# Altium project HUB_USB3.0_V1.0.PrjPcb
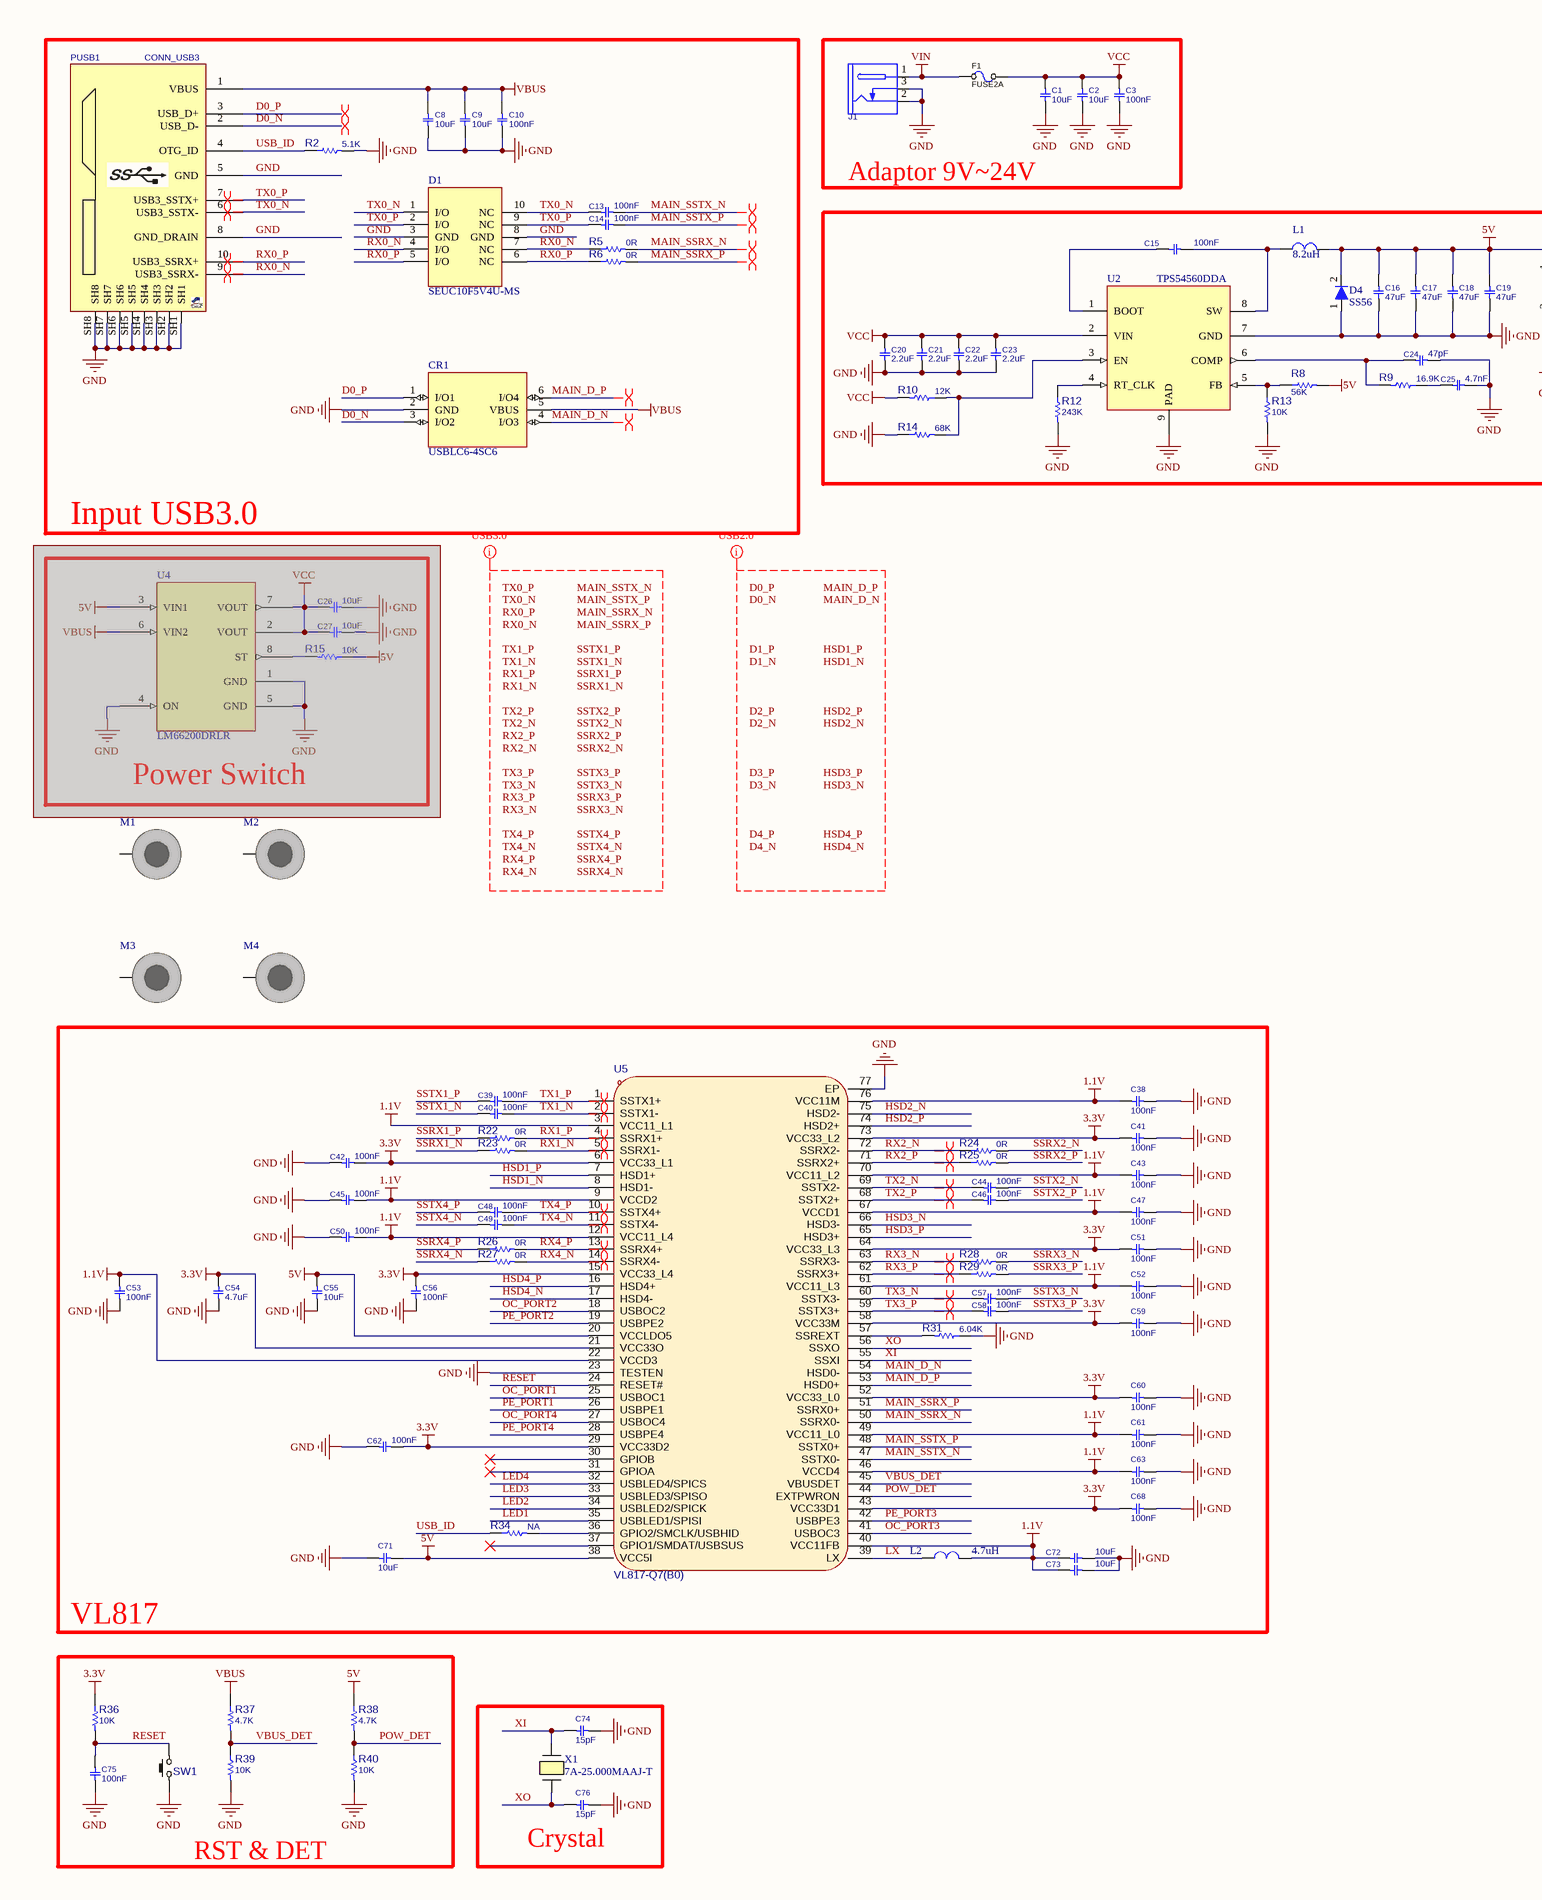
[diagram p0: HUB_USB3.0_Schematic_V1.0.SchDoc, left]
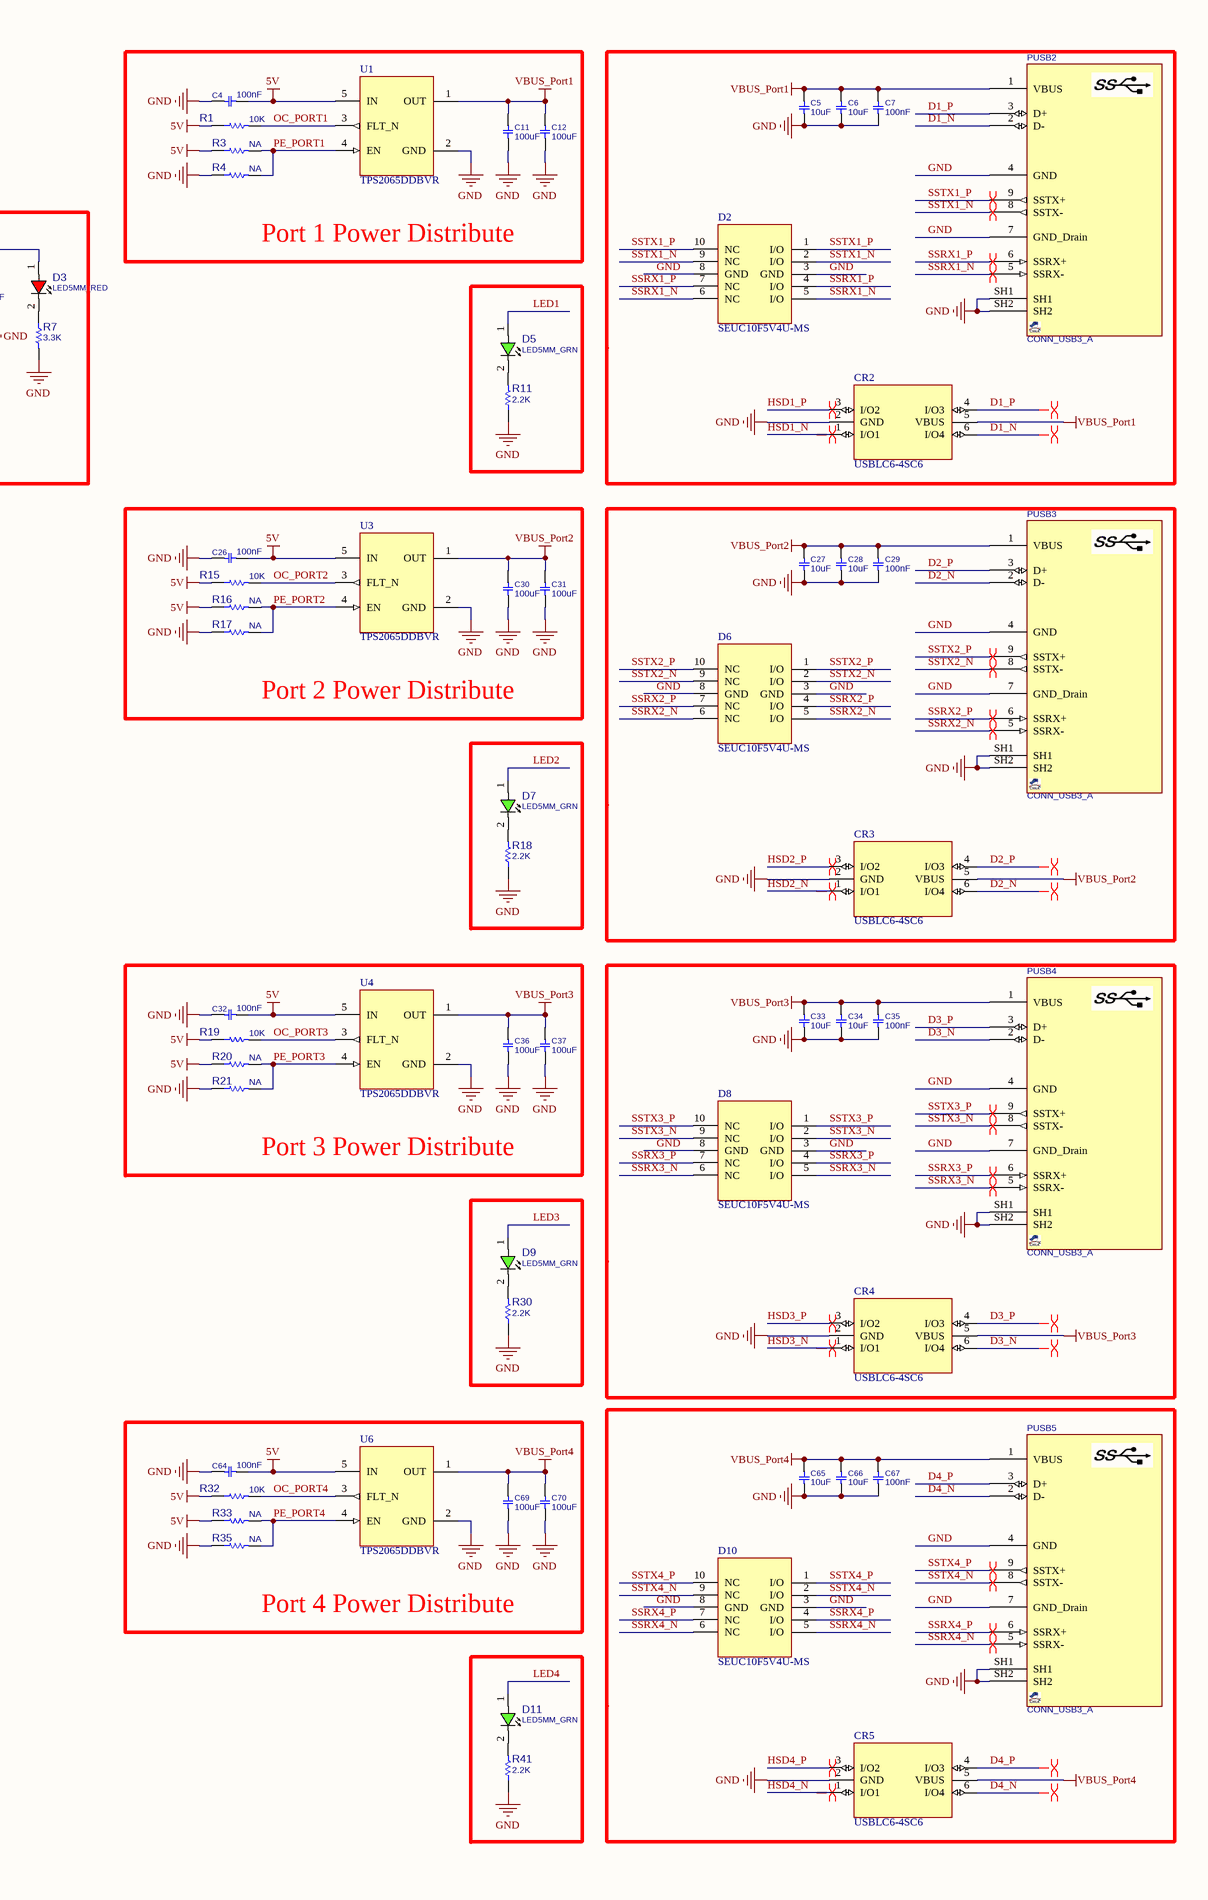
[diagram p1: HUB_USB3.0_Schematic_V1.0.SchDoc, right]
1 sheet, 158 parts. Net scope: global (net labels, ports and power ports of the same name join across sheets).
Board file: HUB_USB3.0_PCB_V1.0.PcbDoc

## Sheet HUB_USB3.0_Schematic_V1.0.SchDoc
size A2; SheetNumber: 1; SheetTotal: 1

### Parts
(Parts that share a designator on the sheet are numbered #1, #2 ... from top to bottom, then left to right.)
C1  10uF  [C0603]
C2  10uF  [C0603]
C3  100nF  [C0603]
C4  100nF  [C0603]
C5  10uF  [C0603]
C6  10uF  [C0603]
C7  100nF  [C0603]
C8  10uF  [C0603]
C9  10uF  [C0603]
C10  100nF  [C0603]
C11  100uF  [C1206]
C12  100uF  [C1206]
C13  100nF  [C0603]
C14  100nF  [C0603]
C15  100nF  [C0603]
C16  47uF  [C0805]
C17  47uF  [C0805]
C18  47uF  [C0805]
C19  47uF  [C0805]
C20  2.2uF  [C0603]
C21  2.2uF  [C0603]
C22  2.2uF  [C0603]
C23  2.2uF  [C0603]
C24  47pF  [C0603]
C25  4.7nF  [C0603]
C26#1  100nF  [C0603]
C26#2  10uF  [C0603]  (masked out: inside a compile mask, not in the netlist)
C27#1  10uF  [C0603]
C27#2  10uF  [C0603]  (masked out: inside a compile mask, not in the netlist)
C28  10uF  [C0603]
C29  100nF  [C0603]
C30  100uF  [C1206]
C31  100uF  [C1206]
C32  100nF  [C0603]
C33  10uF  [C0603]
C34  10uF  [C0603]
C35  100nF  [C0603]
C36  100uF  [C1206]
C37  100uF  [C1206]
C38  100nF  [C0603]
C39  100nF  [C0603]
C40  100nF  [C0603]
C41  100nF  [C0603]
C42  100nF  [C0603]
C43  100nF  [C0603]
C44  100nF  [C0603]
C45  100nF  [C0603]
C46  100nF  [C0603]
C47  100nF  [C0603]
C48  100nF  [C0603]
C49  100nF  [C0603]
C50  100nF  [C0603]
C51  100nF  [C0603]
C52  100nF  [C0603]
C53  100nF  [C0603]
C54  4.7uF  [C0603]
C55  10uF  [C0603]
C56  100nF  [C0603]
C57  100nF  [C0603]
C58  100nF  [C0603]
C59  100nF  [C0603]
C60  100nF  [C0603]
C61  100nF  [C0603]
C62  100nF  [C0603]
C63  100nF  [C0603]
C64  100nF  [C0603]
C65  10uF  [C0603]
C66  10uF  [C0603]
C67  100nF  [C0603]
C68  100nF  [C0603]
C69  100uF  [C1206]
C70  100uF  [C1206]
C71  10uF  [C0603]
C72  10uF  [C0603]
C73  10uF  [C0603]
C74  15pF  [C0603]
C75  100nF  [C0603]
C76  15pF  [C0603]
CR1  USBLC6-4SC6  [SOT23-6L_STM]
CR2  USBLC6-4SC6  [SOT23-6L_STM]
CR3  USBLC6-4SC6  [SOT23-6L_STM]
CR4  USBLC6-4SC6  [SOT23-6L_STM]
CR5  USBLC6-4SC6  [SOT23-6L_STM]
D1  SEUC10F5V4U-MS  [UDFN10_DTS]
D2  SEUC10F5V4U-MS  [UDFN10_DTS]
D3  LED5MM_RED  [LED5MM_RED]
D4  SS56  [DO-214AC]
D5  LED5MM_GRN  [LED5MM_GRN]
D6  SEUC10F5V4U-MS  [UDFN10_DTS]
D7  LED5MM_GRN  [LED5MM_GRN]
D8  SEUC10F5V4U-MS  [UDFN10_DTS]
D9  LED5MM_GRN  [LED5MM_GRN]
D10  SEUC10F5V4U-MS  [UDFN10_DTS]
D11  LED5MM_GRN  [LED5MM_GRN]
F1  FUSE2A  [F2410]
J1  DC_POWER_JACK  [JAC_PWR2]  (value not drawn)
L1  value 8.2uH  [IND_7.3x6.6mm]  (hidden comment: TMPC0603H-8R2MG-D)
L2  value 4.7uH  [IND_SPM6530_TDK]  (hidden comment: SPM6530T-4R7M)
M1  DNP/MH  [SCMH_M3]  (value not drawn)  (no BOM)
M2  DNP/MH  [SCMH_M3]  (value not drawn)  (no BOM)
M3  DNP/MH  [SCMH_M3]  (value not drawn)  (no BOM)
M4  DNP/MH  [SCMH_M3]  (value not drawn)  (no BOM)
PUSB1  CONN_USB3  [USB3_MICRO_B]
PUSB2  CONN_USB3_A  [USB3_A_RA]
PUSB3  CONN_USB3_A  [USB3_A_RA]
PUSB4  CONN_USB3_A  [USB3_A_RA]
PUSB5  CONN_USB3_A  [USB3_A_RA]
R1  10K  [R0603]
R2  5.1K  [R0603]
R3  NA  [R0603]  (no BOM)
R4  NA  [R0603]  (no BOM)
R5  0R  [R0603]
R6  0R  [R0603]
R7  3.3K  [R0603]
R8  56K  [R0603]
R9  16.9K  [R0603]
R10  12K  [R0603]
R11  2.2K  [R0603]
R12  243K  [R0603]
R13  10K  [R0603]
R14  68K  [R0603]
R15#1  10K  [R0603]
R15#2  10K  [R0603]  (masked out: inside a compile mask, not in the netlist)
R16  NA  [R0603]  (no BOM)
R17  NA  [R0603]  (no BOM)
R18  2.2K  [R0603]
R19  10K  [R0603]
R20  NA  [R0603]  (no BOM)
R21  NA  [R0603]  (no BOM)
R22  0R  [R0603]
R23  0R  [R0603]
R24  0R  [R0603]
R25  0R  [R0603]
R26  0R  [R0603]
R27  0R  [R0603]
R28  0R  [R0603]
R29  0R  [R0603]
R30  2.2K  [R0603]
R31  6.04K  [R0603]
R32  10K  [R0603]
R33  NA  [R0603]  (no BOM)
R34  NA  [R0603]  (no BOM)
R35  NA  [R0603]  (no BOM)
R36  10K  [R0603]
R37  4.7K  [R0603]
R38  4.7K  [R0603]
R39  10K  [R0603]
R40  10K  [R0603]
R41  2.2K  [R0603]
SW1  PUSHBUTTON  [SWPBT_SPST_R_6X6X4]  (value not drawn)
U1  TPS2065DDBVR  [DBV0005A_N]
U2  TPS54560DDA  [DDA0008E_N]
U3  TPS2065DDBVR  [DBV0005A_N]
U4#1  LM66200DRLR  [SOT-5X3_DRL_TEX]  (masked out: inside a compile mask, not in the netlist)
U4#2  TPS2065DDBVR  [DBV0005A_N]
U5  VL817-Q7(B0)  [QFN-76_L9.0-W9.0-P0.40-BL-EP]
U6  TPS2065DDBVR  [DBV0005A_N]
X1  7A-25.000MAAJ-T  [CRYSTAL_TXC_7A_TXC]

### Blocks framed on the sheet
Input USB3.0: C8-C10 C13 C14 CR1 D1 PUSB1 R2 R5 R6
Adaptor 9V~24V: C1-C3 F1 J1
Port 1 Power Distribute: C4 C11 C12 R1 R3 R4 U1
Port 2 Power Distribute: C26#1 C30 C31 R15#1 R16 R17 U3
Power Switch: C26#2 C27#2 R15#2 U4#1
Port 3 Power Distribute: C32 C36 C37 R19-R21 U4#2
VL817: C38-C63 C68 C71-C73 L2 R22-R29 R31 R34 U5
Port 4 Power Distribute: C64 C69 C70 R32 R33 R35 U6
RST & DET: C75 R36-R40 SW1
Crystal: C74 C76 X1

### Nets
1.1V: C38.2 C43.2 C45.2 C47.2 C50.2 C52.2 C53.2 C61.2 C63.2 C72.1 C73.1 L2.2 U5.3(VCC11_L1) U5.9(VCCD2) U5.12(VCC11_L4) U5.22(VCCD3) U5.40(VCC11FB) U5.46(VCCD4) U5.49(VCC11_L0) U5.61(VCC11_L3) U5.67(VCCD1) U5.70(VCC11_L2) U5.76(VCC11M)
3.3V: C41.2 C42.2 C51.2 C54.2 C56.2 C59.2 C60.2 C62.2 C68.2 R36.1 U5.6(VCC33_L1) U5.15(VCC33_L4) U5.21(VCC33O) U5.29(VCC33D2) U5.43(VCC33D1) U5.52(VCC33_L0) U5.58(VCC33M) U5.64(VCC33_L3) U5.73(VCC33_L2)
5V: C4.2 C16.2 C17.2 C18.2 C19.2 C26#1.2 C32.2 C55.2 C64.2 C71.1 D3.1(ANODE) D4.2(K) L1.2 R1.1 R3.1 R8.2 R15#1.1 R16.1 R19.1 R20.1 R32.1 R33.1 R38.1 U1.5(IN) U3.5(IN) U4#2.5(IN) U5.20(VCCLDO5) U5.38(VCC5I) U6.5(IN)
GND: C1.2 C2.2 C3.2 C4.1 C5.2 C6.2 C7.2 C8.2 C9.2 C10.2 C11.1 C12.1 C16.1 C17.1 C18.1 C19.1 C20.1 C21.1 C22.1 C23.1 C24.2 C25.2 C26#1.1 C27#1.2 C28.2 C29.2 C30.1 C31.1 C32.1 C33.2 C34.2 C35.2 C36.1 C37.1 C38.1 C41.1 C42.1 C43.1 C45.1 C47.1 C50.1 C51.1 C52.1 C53.1 C54.1 C55.1 C56.1 C59.1 C60.1 C61.1 C62.1 C63.1 C64.1 C65.2 C66.2 C67.2 C68.1 C69.1 C70.1 C71.2 C72.2 C73.2 C74.2 C75.1 C76.2 CR1.2(GND) CR2.2(GND) CR3.2(GND) CR4.2(GND) CR5.2(GND) D1.3(GND) D1.8(GND) D2.3(GND) D2.8(GND) D4.1(A) D6.3(GND) D6.8(GND) D8.3(GND) D8.8(GND) D10.3(GND) D10.8(GND) J1.2(SLEEVE) J1.3(INSERTION_DET) PUSB1.5(GND) PUSB1.8(GND_DRAIN) PUSB1.SH1 PUSB1.SH2 PUSB1.SH3 PUSB1.SH4 PUSB1.SH5 PUSB1.SH6 PUSB1.SH7 PUSB1.SH8 PUSB2.4(GND) PUSB2.7(GND_Drain) PUSB2.SH1 PUSB2.SH2 PUSB3.4(GND) PUSB3.7(GND_Drain) PUSB3.SH1 PUSB3.SH2 PUSB4.4(GND) PUSB4.7(GND_Drain) PUSB4.SH1 PUSB4.SH2 PUSB5.4(GND) PUSB5.7(GND_Drain) PUSB5.SH1 PUSB5.SH2 R2.2 R4.1 R7.2 R11.1 R12.2 R13.2 R14.1 R17.1 R18.1 R21.1 R30.1 R31.1 R35.1 R39.2 R40.2 R41.1 SW1.1 U1.2(GND) U2.7(GND) U2.9(PAD) U3.2(GND) U4#2.2(GND) U5.23(TESTEN) U5.77(EP) U6.2(GND)
VBUS: C8.1 C9.1 C10.1 CR1.5(VBUS) PUSB1.1(VBUS) R37.1
VBUS_Port1: C5.1 C6.1 C7.1 C11.2 C12.2 CR2.5(VBUS) PUSB2.1(VBUS) U1.1(OUT)
VBUS_Port2: C27#1.1 C28.1 C29.1 C30.2 C31.2 CR3.5(VBUS) PUSB3.1(VBUS) U3.1(OUT)
VBUS_Port3: C33.1 C34.1 C35.1 C36.2 C37.2 CR4.5(VBUS) PUSB4.1(VBUS) U4#2.1(OUT)
VBUS_Port4: C65.1 C66.1 C67.1 C69.2 C70.2 CR5.5(VBUS) PUSB5.1(VBUS) U6.1(OUT)
VCC: C1.1 C2.1 C3.1 C20.2 C21.2 C22.2 C23.2 F1.2 R10.2 U2.2(VIN)
VIN: F1.1 J1.1(TIP)
D0_N: CR1.3(I/O2) PUSB1.2(USB_D-)
D0_P: CR1.1(I/O1) PUSB1.3(USB_D+)
D1_N: CR2.6(I/O4) PUSB2.2(D-)
D1_P: CR2.4(I/O3) PUSB2.3(D+)
D2_N: CR3.6(I/O4) PUSB3.2(D-)
D2_P: CR3.4(I/O3) PUSB3.3(D+)
D3_N: CR4.6(I/O4) PUSB4.2(D-)
D3_P: CR4.4(I/O3) PUSB4.3(D+)
D4_N: CR5.6(I/O4) PUSB5.2(D-)
D4_P: CR5.4(I/O3) PUSB5.3(D+)
HSD1_N: CR2.1(I/O1) U5.8(HSD1-)
HSD1_P: CR2.3(I/O2) U5.7(HSD1+)
HSD2_N: CR3.1(I/O1) U5.75(HSD2-)
HSD2_P: CR3.3(I/O2) U5.74(HSD2+)
HSD3_N: CR4.1(I/O1) U5.66(HSD3-)
HSD3_P: CR4.3(I/O2) U5.65(HSD3+)
HSD4_N: CR5.1(I/O1) U5.17(HSD4-)
HSD4_P: CR5.3(I/O2) U5.16(HSD4+)
LED1: D5.1(ANODE) U5.35(USBLED1/SPISI)
LED2: D7.1(ANODE) U5.34(USBLED2/SPICK)
LED3: D9.1(ANODE) U5.33(USBLED3/SPISO)
LED4: D11.1(ANODE) U5.32(USBLED4/SPICS)
LX: L2.1 U5.39(LX)
MAIN_D_N: CR1.4(I/O3) U5.54(HSD0-)
MAIN_D_P: CR1.6(I/O4) U5.53(HSD0+)
MAIN_SSRX_N: R5.2 U5.50(SSRX0-)
MAIN_SSRX_P: R6.2 U5.51(SSRX0+)
MAIN_SSTX_N: C13.2 U5.47(SSTX0-)
MAIN_SSTX_P: C14.2 U5.48(SSTX0+)
OC_PORT1: R1.2 U1.3(FLT_N) U5.25(USBOC1)
OC_PORT2: R15#1.2 U3.3(FLT_N) U5.18(USBOC2)
OC_PORT3: R19.2 U4#2.3(FLT_N) U5.41(USBOC3)
OC_PORT4: R32.2 U5.27(USBOC4) U6.3(FLT_N)
PE_PORT1: R3.2 R4.2 U1.4(EN) U5.26(USBPE1)
PE_PORT2: R16.2 R17.2 U3.4(EN) U5.19(USBPE2)
PE_PORT3: R20.2 R21.2 U4#2.4(EN) U5.42(USBPE3)
PE_PORT4: R33.2 R35.2 U5.28(USBPE4) U6.4(EN)
POW_DET: R38.2 R40.1 U5.44(EXTPWRON)
RESET: C75.2 R36.2 SW1.2 U5.24(RESET#)
RX0_N: D1.4(I/O) D1.7(NC) PUSB1.9(USB3_SSRX-) R5.1
RX0_P: D1.5(I/O) D1.6(NC) PUSB1.10(USB3_SSRX+) R6.1
RX1_N: R23.2 U5.5(SSRX1-)
RX1_P: R22.2 U5.4(SSRX1+)
RX2_N: R24.1 U5.72(SSRX2-)
RX2_P: R25.1 U5.71(SSRX2+)
RX3_N: R28.1 U5.63(SSRX3-)
RX3_P: R29.1 U5.62(SSRX3+)
RX4_N: R27.2 U5.14(SSRX4-)
RX4_P: R26.2 U5.13(SSRX4+)
SSRX1_N: D2.5(I/O) D2.6(NC) PUSB2.5(SSRX-) R23.1
SSRX1_P: D2.4(I/O) D2.7(NC) PUSB2.6(SSRX+) R22.1
SSRX2_N: D6.5(I/O) D6.6(NC) PUSB3.5(SSRX-) R24.2
SSRX2_P: D6.4(I/O) D6.7(NC) PUSB3.6(SSRX+) R25.2
SSRX3_N: D8.5(I/O) D8.6(NC) PUSB4.5(SSRX-) R28.2
SSRX3_P: D8.4(I/O) D8.7(NC) PUSB4.6(SSRX+) R29.2
SSRX4_N: D10.5(I/O) D10.6(NC) PUSB5.5(SSRX-) R27.1
SSRX4_P: D10.4(I/O) D10.7(NC) PUSB5.6(SSRX+) R26.1
SSTX1_N: C40.1 D2.2(I/O) D2.9(NC) PUSB2.8(SSTX-)
SSTX1_P: C39.1 D2.1(I/O) D2.10(NC) PUSB2.9(SSTX+)
SSTX2_N: C44.2 D6.2(I/O) D6.9(NC) PUSB3.8(SSTX-)
SSTX2_P: C46.2 D6.1(I/O) D6.10(NC) PUSB3.9(SSTX+)
SSTX3_N: C57.2 D8.2(I/O) D8.9(NC) PUSB4.8(SSTX-)
SSTX3_P: C58.2 D8.1(I/O) D8.10(NC) PUSB4.9(SSTX+)
SSTX4_N: C49.1 D10.2(I/O) D10.9(NC) PUSB5.8(SSTX-)
SSTX4_P: C48.1 D10.1(I/O) D10.10(NC) PUSB5.9(SSTX+)
TX0_N: C13.1 D1.1(I/O) D1.10(NC) PUSB1.6(USB3_SSTX-)
TX0_P: C14.1 D1.2(I/O) D1.9(NC) PUSB1.7(USB3_SSTX+)
TX1_N: C40.2 U5.2(SSTX1-)
TX1_P: C39.2 U5.1(SSTX1+)
TX2_N: C44.1 U5.69(SSTX2-)
TX2_P: C46.1 U5.68(SSTX2+)
TX3_N: C57.1 U5.60(SSTX3-)
TX3_P: C58.1 U5.59(SSTX3+)
TX4_N: C49.2 U5.11(SSTX4-)
TX4_P: C48.2 U5.10(SSTX4+)
USB_ID: PUSB1.4(OTG_ID) R2.1 R34.1
VBUS_DET: R37.2 R39.1 U5.45(VBUSDET)
XI: C74.1 U5.55(SSXI) X1.2
XO: C76.1 U5.56(SSXO) X1.1
NetC15_1: C15.1 L1.1 U2.8(SW)
NetC15_2: C15.2 U2.1(BOOT)
NetC24_1: C24.1 R9.2 U2.6(COMP)
NetC25_1: C25.1 R9.1
NetD3_2: D3.2(CATHODE) R7.1
NetD5_2: D5.2(CATHODE) R11.2
NetD7_2: D7.2(CATHODE) R18.2
NetD9_2: D9.2(CATHODE) R30.2
NetD11_2: D11.2(CATHODE) R41.2
NetR8_1: R8.1 R13.1 U2.5(FB)
NetR10_1: R10.1 R14.2 U2.3(EN)
NetR12_1: R12.1 U2.4(RT_CLK)
NetR31_2: R31.2 U5.57(SSREXT)
NetR34_2: R34.2 U5.36(GPIO2/SMCLK/USBHID)

Not connected (* = marked no-connect by the designer): M1 1; M2 1; M3 1; M4 1; U5 30(GPIOB)* 31(GPIOA)* 37(GPIO1/SMDAT/USBSUS)*

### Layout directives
differential pair: D0_N, D0_P, D1_N, D1_P, D2_N, D2_P, D3_N, D3_P, D4_N, D4_P, HSD1_N, HSD1_P, HSD2_N, HSD2_P, HSD3_N, HSD3_P, HSD4_N, HSD4_P, MAIN_D_N, MAIN_D_P, MAIN_SSRX_N, MAIN_SSRX_P, MAIN_SSTX_N, MAIN_SSTX_P, RX0_N, RX0_P, RX1_N, RX1_P, RX2_N, RX2_P, RX3_N, RX3_P, RX4_N, RX4_P, SSRX1_N, SSRX1_P, SSRX2_N, SSRX2_P, SSRX3_N, SSRX3_P, SSRX4_N, SSRX4_P, SSTX1_N, SSTX1_P, SSTX2_N, SSTX2_P, SSTX3_N, SSTX3_P, SSTX4_N, SSTX4_P, TX0_N, TX0_P, TX1_N, TX1_P, TX2_N, TX2_P, TX3_N, TX3_P, TX4_N, TX4_P
net class USB3.0: MAIN_SSRX_N, MAIN_SSRX_P, MAIN_SSTX_N, MAIN_SSTX_P, RX0_N, RX0_P, RX1_N, RX1_P, RX2_N, RX2_P, RX3_N, RX3_P, RX4_N, RX4_P, SSRX1_N, SSRX1_P, SSRX2_N, SSRX2_P, SSRX3_N, SSRX3_P, SSRX4_N, SSRX4_P, SSTX1_N, SSTX1_P, SSTX2_N, SSTX2_P, SSTX3_N, SSTX3_P, SSTX4_N, SSTX4_P, TX0_N, TX0_P, TX1_N, TX1_P, TX2_N, TX2_P, TX3_N, TX3_P, TX4_N, TX4_P
net class USB2.0: D0_N, D0_P, D1_N, D1_P, D2_N, D2_P, D3_N, D3_P, D4_N, D4_P, HSD1_N, HSD1_P, HSD2_N, HSD2_P, HSD3_N, HSD3_P, HSD4_N, HSD4_P, MAIN_D_N, MAIN_D_P

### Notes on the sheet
- Labels drawn without touching a wire or pin: D0_N, D0_P, D1_N, D1_P, D2_N, D2_P, D3_N, D3_P, D4_N, D4_P, HSD1_N, HSD1_P, HSD2_N, HSD2_P, HSD3_N, HSD3_P, HSD4_N, HSD4_P, MAIN_D_N, MAIN_D_P, MAIN_SSRX_N, MAIN_SSRX_P, MAIN_SSTX_N, MAIN_SSTX_P, RX0_N, RX0_P, RX1_N, RX1_P, RX2_N, RX2_P, RX3_N, RX3_P, RX4_N, RX4_P, SSRX1_N, SSRX1_P, SSRX2_N, SSRX2_P, SSRX3_N, SSRX3_P, SSRX4_N, SSRX4_P, SSTX1_N, SSTX1_P, SSTX2_N, SSTX2_P, SSTX3_N, SSTX3_P, SSTX4_N, SSTX4_P, TX0_N, TX0_P, TX1_N, TX1_P, TX2_N, TX2_P, TX3_N, TX3_P, TX4_N, TX4_P

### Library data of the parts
C1 C2 C5 C6 C8 C9 C16-C19 C26#2 C27#1 C27#2 C28 C33 C34 C54 C55 C65 C66 C71-C73 = CAP_SMD_MLCC_0805: CAP, MLCC; PARAM: -, -%; MANF_P#: MANF_PART#; PARAM2: -V
C3 C4 C7 C10 C13-C15 C20-C25 C26#1 C29 C32 C35 C38-C53 C56-C64 C67 C68 C74-C76 = CAP_SMD_MLCC_0603: CAP, MLCC; PARAM: -, -%; MANF_P#: MANF_PART#; PARAM2: -V
C11 C12 C30 C31 C36 C37 C69 C70 = CAP_SMD_MLCC_1206: CAP, MLCC; PARAM: -, -%; MANF_P#: MANF_PART#; PARAM2: -V
CR1-CR5 = USBLC6-4SC6: Very low capacitance ESD protection; Manufacturer_Name: STMicroelectronics
D1 D2 D6 D8 D10 = SEUC10F5V4U-MS: 4Line Bidirectional ESD Protection for High Speed Interfaces; Manufacturer_Name: onsemi; Manufacturer_Part_Number: ESD8104MUTAG
D3 = LED_THD_5MM_RED: LED, THD, 5MM, RED; DESC: DESCRIPTION; MANF_P#: MANF_PART#; PARAM2: 2.2V
D4 = SS56: Schottky Diode 60V 5A SMA
D5 D7 D9 D11 = LED_THD_5MM_GRN: LED, THD, 5MM, GREEN; DESC: DESCRIPTION; MANF_P#: MANF_PART#; PARAM2: 2.2V
F1 = FUSE_2A_2410: Fuse, 2A, 125VDC, 2410, SMD, Fast Acting; PARAM: 2A; 125VDC; fast acting; MANF: Reomax; MANF_P#: SFE1200; PARAM2: 0.25 Ohm DC Cold Resistance
J1 = CONN_PWR_JACKR2: CONN, PWR JACK DC, PLUG DIAM 2.0MM RA THD; MANF: CUI STACK; MANF_P#: PJ-202A, PJ-002AH, PJ-102AH, KLDX-0202
L1 = IND_TMPC0603H-8R2MG-D: SMD Power Choke Coil 8.2uH 7.5A 7.3x6.6mm
L2 = SPM6530T-4R7M: SMD Inductor 4.7uH 6.2A 6530; Manufacturer_Name: TDK
M1-M4 = SCMH_M3: SCREW mouting, M3, 3.0mm diameter and 6.0mm PanHead; ASSEMBLY: DNP
PUSB1 = CONN_USB3_MICRO_B: CONN, USB3, MICRO B, SMD; MANF_P#: GSB343133HR; MANF: Amphenol; MANF_P#2: CMS1811-010010 (HOSIDEN)
PUSB2-PUSB5 = CONN_USB3_A_USB1075: CONN, USB3, A type, R/A, THD; MANF: GCT; PARAM2: 5,000 cycles; PARAM: 1.8A, -55~+85°C
R1-R14 R15#1 R15#2 R16-R41 = RES_SMD_0603: RESISTOR, SMD; PARAM: 1%, 0.1W; DESC: DESCRIPTION; DIST#: MOUSER
SW1 = SWPBT_SPST_R_6X6_G: SWITCH, PUSH BUTTON, TACTILE, THD, SPST, RIGHT; MANF: Grayhill; PARAM: 50mA/12VDC; DESC: DESCRIPTION; MANF_P#: 95C06A2RAT, 95C06A3RAT, 95C06C2RAT
U1 U3 U4#2 U6 = TPS2065DDBVR: 1A loading, 4.5-5.5V, 96mÎ© USB power switch, active-high, output discharge, reverse blocking 5-SOT-23 -40 to 125; Manufacturer_Name: Texas Instruments
U2 = TPS54560DDA: 4.5V to 60 V input, 5 A step-down converter with Eco-Mode 8-SO PowerPAD 0 to 0; Manufacturer_Name: Texas Instruments
U4#1 = LM66200DRLR: 1.6-V to 5.5-V, 40-mâ„¦, 2.5-A, low-IQ, dual ideal diode 8-SOT-5X3 -40 to 125; Manufacturer_Name: Texas Instruments
U5 = VL817-Q7(B0): Applications Function:USB Hub USB Protocol:USB 3.1；USB 2.0 Number of Channels:4 Voltage - Supply:3V~3.6V；1V~1.2V Voltage - Supply:3V~3.6V；1V~1.2V Data Rate:5Gbps Operating Temperature:0℃~+70℃ Operating Temperature:0℃~+70℃ Current - Supply:- Quiescent Supp; Manufacturer: VIA Labs(威锋电子); AddInBom: yes; ModelId: 0f9422e5a91044218abe04bb719ae7d6ÂŽ0819f05c4eef4c71ace90d822a990e87; ModelName: QFN-76_L9.0-W9.0-H0.9-P0.40-BL-EP; ModelTransform: 354.33,354.33,0,0,0,0,0,0,0; Applications Function: USB Hub; Number of Channels: 4; Data Rate: 5Gbps
X1 = 7A-25.000MAAJ-T: 25MHz 12pF ±30ppm SMD5032-4P Crystals; Manufacturer_Name: TXC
